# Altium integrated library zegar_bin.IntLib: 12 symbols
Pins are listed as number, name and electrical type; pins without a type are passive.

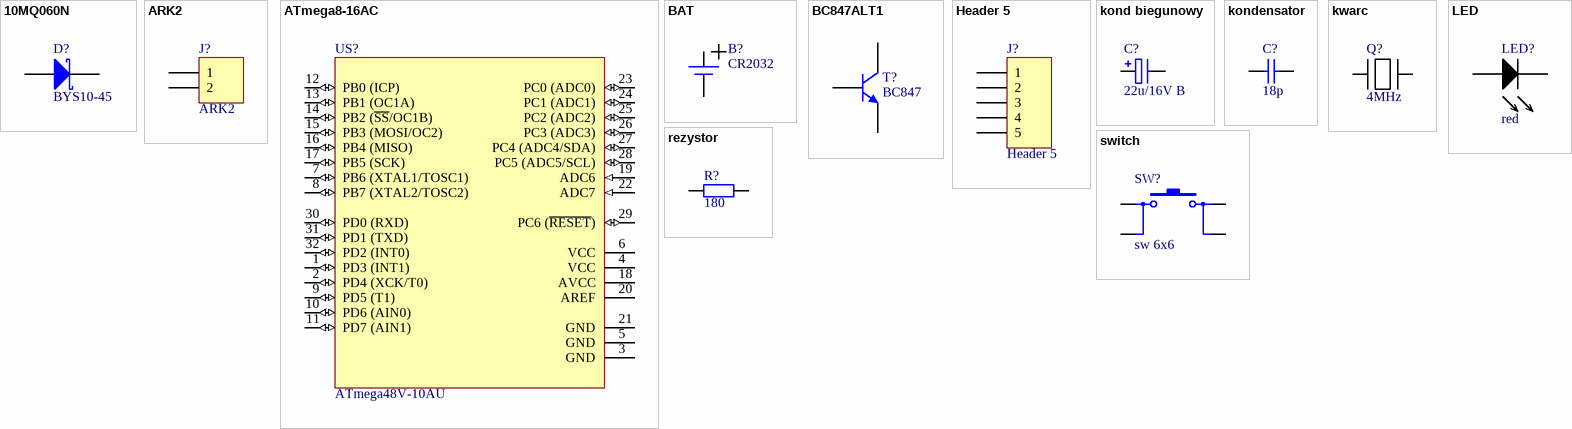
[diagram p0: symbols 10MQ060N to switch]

## 10MQ060N
designator D?, comment BYS10-45
Schottky Rectifier; PackageDocument: revH, May-2002
footprint SMA (DO-214-AC/SMA; 2 C-Bend Leads; Body 5 x 2.7 mm, inc. leads (LxW))
simulation model 10MQ060N (DIODE)
pins: 1 A, 2 K

## ARK2
designator J?
footprint ARK2 3,5mm
footprint ARK2 5mm
footprint ARK2 7,5mm
pins: 1, 2

## ATmega8-16AC
designator US?, comment ATmega48V-10AU
8-Bit AVR Microcontroller with 8K Bytes of In-System Programmable Flash Memory
footprint 32A_N (Thin QFP, 32-Leads, Body 7x7mm, Pitch 0.8mm, IPC Medium Density)
footprint 32A_L (Thin QFP, 32-Leads, Body 7x7mm, Pitch 0.8mm, IPC High Density)
footprint 32A_M (Thin QFP, 32-Leads, Body 7x7mm, Pitch 0.8mm, IPC Low Density)
3D model ATMEGA8-32A (32-Pin Thin Quad Flat Pack 0.8 mm Pitch)
pins: 1 PD3 (INT1) (io), 2 PD4 (XCK/T0) (io), 3 GND (power), 4 VCC (power), 5 GND (power), 6 VCC (power), 7 PB6 (XTAL1/TOSC1) (io), 8 PB7 (XTAL2/TOSC2) (io), 9 PD5 (T1) (io), 10 PD6 (AIN0) (io), 11 PD7 (AIN1) (io), 12 PB0 (ICP) (io), 13 PB1 (OC1A) (io), 14 PB2 (~{SS}/OC1B) (io), 15 PB3 (MOSI/OC2) (io), 16 PB4 (MISO) (io), 17 PB5 (SCK) (io), 18 AVCC (power), 19 ADC6 (in), 20 AREF, 21 GND (power), 22 ADC7 (in), 23 PC0 (ADC0) (io), 24 PC1 (ADC1) (io), 25 PC2 (ADC2) (io), 26 PC3 (ADC3) (io), 27 PC4 (ADC4/SDA) (io), 28 PC5 (ADC5/SCL) (io), 29 PC6 (~{RESET}) (io), 30 PD0 (RXD) (io), 31 PD1 (TXD) (io), 32 PD2 (INT0) (io)

## BAT
designator B?, comment CR2032
footprint CR20xx THT
footprint CR2032 SMD BC-2001
footprint CR2032 THT BC-2002
pins: 1 +, 2 -

## BC847ALT1
designator T?, comment BC847
General Purpose Transistor NPN Silicon
footprint 318-08 (SOT-23; 3 Leads; Body 3.0 x 2.6 mm, inc. leads (LxW max))
simulation model BC847ALT1 (NPN)
signal-integrity model BC847ALT1
pins: 1 B, 2 E, 3 C

## Header 5
designator J?
Header, 5-Pin
footprint HDR1X5 (Connector; Header; 5 Position)
signal-integrity model Connector
pins: 1, 2, 3, 4, 5

## kond biegunowy
designator C?, comment 22u/16V B
Polarized Capacitor
footprint Tantal B 3528-1411 (Capacitor, SM Tantalum; Body 3.5 x 2.8 mm (LxW typ))
footprint Tantal C 6032-2412 (Capacitor, SM Tantalum; Body 6.0 x 3.2 mm (LxW typ))
footprint Tantal D 7343-2917 (Capacitor, SM Tantalum; Body 7.3 x 4.3 mm (LxW typ))
footprint 2,5/5mm elektrolit
footprint 3,5/7mm elektrolit
footprint 5/10mm elektrolit
footprint 2,5/7mm elektrolit
footprint 7,5/16mm elektrolit
footprint 5/12,5mm elektrolit
footprint Tantal A 3216-1206 (Capacitor, SM Tantalum; Body 3.2 x 1.6 mm (LxW typ))
footprint A SMD elektrolit
footprint B SMD elektrolit
footprint C SMD elektrolit
footprint D SMD elektrolit
footprint E SMD elektrolit
footprint F SMD elektrolit
footprint 2,5/7mm le抗cy elektrolit
footprint 5/10mm le抗cy elektrolit
pins: 1, 2
1 alternate drawing of the same symbol

## kondensator
designator C?, comment 18p
Value: 100n
footprint kond 2,5mm
footprint kond 7,5mm
footprint kond 10mm
footprint MELF-0805 (Metal Electrode Face (MELF) Resistor; Body 2 x 1.4 mm (LxDia))
footprint MELF-1206 (Metal Electrode Face (MELF) Resistor; Body 3.2 x 1.8 mm (LxDia))
footprint kond 15mm
footprint kond 5mm chudy
footprint kond 5mm gruby
footprint kond 5mm sredni
pins: 1, 2

## kwarc
designator Q?, comment 4MHz
footprint kwarc 5mm
footprint kwarc HC49
footprint kwarc 91SMX SMD
footprint kwarc 32768 le抗cy
footprint kwarc 32768 stojacy
pins: 1, 2

## LED
designator LED?, comment red
footprint LED 3mm
footprint LED 5mm
footprint MELF-1206 LED (Metal Electrode Face (MELF) Resistor; Body 3.2 x 1.8 mm (LxDia))
pins: A, K

## rezystor
designator R?, comment 180
footprint rez 7,5mm
footprint rez 10mm
footprint rez 12,5mm
footprint rez 15mm
footprint rez 17,5mm
footprint MELF-0805 (Metal Electrode Face (MELF) Resistor; Body 2 x 1.4 mm (LxDia))
footprint MELF-1206 (Metal Electrode Face (MELF) Resistor; Body 3.2 x 1.8 mm (LxDia))
footprint rez_bocznik 20mm
footprint rez_5W kostka
pins: 1, 2

## switch
designator SW?, comment sw 6x6
footprint tact switch 12x12
footprint tact switch 6x6
pins: 1, 2, 3, 4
